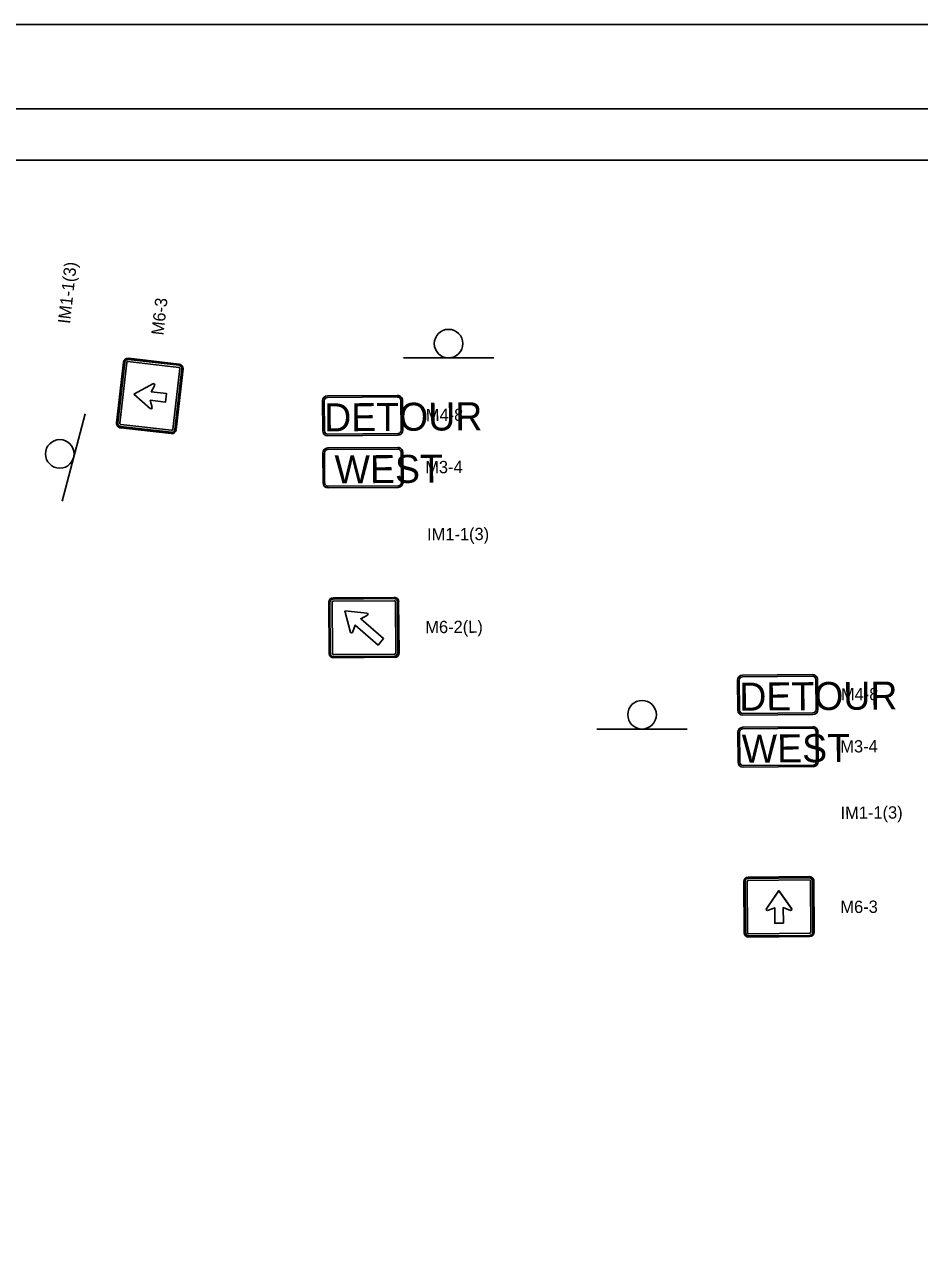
# Model space of a CAD drawing. Extents: x 2162123 to 2216123, y 180770 to 216770.
# Drawn here: x 2190113 to 2203225, y 198770 to 216770 of the extents above; entities that cross this region are included whole.
import ezdxf

# ---------------------------------------------------------------- set-up
doc = ezdxf.new("R2010")
doc.units = 0
for name, color, linetype in [('Default', 7, 'Continuous'), ('PR_Phasing_Detour_1', 7, 'Continuous'), ('SHT_Plot_Shape_Full', 7, 'Continuous'), ('SHT_Plot_Shape_Half', 7, 'Continuous'), ('SHT_Section_Layout_Block', 7, 'Continuous'), ('SHT_Sheet_Border', 7, 'Continuous')]:
    doc.layers.add(name, color=color, linetype=linetype)

# ---------------------------------------------------------------- blocks, each defined once
blk = doc.blocks.new('PRSIGN')
at = {"layer": 'Default'}
blk.add_line((20.04, 6.36), (-20.04, 6.36), dxfattribs=at)
blk.add_circle((0, 0), 6.35, dxfattribs=at)

msp = doc.modelspace()

# ---------------------------------------------------------------- linework, layer by layer
at = {"layer": 'PR_Phasing_Detour_1'}
for p, q in [((2192378, 211793), (2191634, 211877)), ((2191562, 211820), (2191461, 210930)), ((2191580, 211818), (2191479, 210928)), ((2191580, 211818), (2191479, 210928)), ((2191510, 210924), (2191610, 211814)), ((2191510, 210924), (2191610, 211814)), ((2191628, 211828), (2192373, 211744)), ((2191628, 211828), (2192373, 211744)), ((2192376, 211775), (2191632, 211859)), ((2192376, 211775), (2191632, 211859)), ((2192387, 211726), (2192286, 210836)), ((2192387, 211726), (2192286, 210836)), ((2192317, 210833), (2192417, 211723)), ((2192317, 210833), (2192417, 211723)), ((2192335, 210831), (2192435, 211721)), ((2192002, 211508), (2191712, 211352)), ((2191712, 211352), (2191960, 211136)), ((2191967, 211386), (2192020, 211485)), ((2192192, 211361), (2191967, 211386)), ((2192178, 211236), (2192192, 211361)), ((2195577, 211334), (2194551, 211326)), ((2191983, 211154), (2191953, 211262)), ((2191953, 211262), (2192178, 211236)), ((2194478, 211252), (2194482, 210813)), ((2194503, 211253), (2194506, 210813)), ((2195577, 211310), (2194551, 211302)), ((2195630, 210822), (2195626, 211262)), ((2195654, 210822), (2195651, 211262)), ((2191518, 210858), (2192263, 210774)), ((2191521, 210876), (2192265, 210792)), ((2191521, 210876), (2192265, 210792)), ((2192268, 210822), (2191524, 210906)), ((2192268, 210822), (2191524, 210906)), ((2194556, 210765), (2195581, 210773)), ((2194556, 210740), (2195581, 210748)), ((2194482, 210489), (2194486, 210049)), ((2194507, 210489), (2194510, 210049)), ((2195581, 210571), (2194555, 210563)), ((2195581, 210546), (2194555, 210538)), ((2195634, 210058), (2195630, 210498)), ((2195658, 210059), (2195655, 210498)), ((2194560, 210001), (2195585, 210009)), ((2194560, 209976), (2195585, 209985)), ((2194569, 208300), (2194575, 207551)), ((2194587, 208300), (2194593, 207551)), ((2194587, 208300), (2194593, 207551)), ((2194624, 207551), (2194618, 208300)), ((2194624, 207551), (2194618, 208300)), ((2195529, 208373), (2194633, 208365)), ((2195529, 208354), (2194633, 208347)), ((2195529, 208354), (2194633, 208347)), ((2194634, 208317), (2195529, 208324)), ((2194634, 208317), (2195529, 208324)), ((2195546, 208308), (2195552, 207559)), ((2195546, 208308), (2195552, 207559)), ((2195582, 207559), (2195576, 208308)), ((2195582, 207559), (2195576, 208308)), ((2195601, 207559), (2195594, 208308)), ((2195135, 208140), (2194808, 208175)), ((2194808, 208175), (2194890, 207856)), ((2195536, 207542), (2194640, 207535)), ((2195536, 207542), (2194640, 207535)), ((2194640, 207505), (2195536, 207512)), ((2194640, 207505), (2195536, 207512)), ((2194640, 207486), (2195536, 207494)), ((2201659, 207241), (2200633, 207232)), ((2201659, 207216), (2200633, 207208)), ((2200560, 207159), (2200564, 206719)), ((2200585, 207159), (2200588, 206719)), ((2201712, 206728), (2201708, 207168)), ((2201736, 206728), (2201733, 207168)), ((2200638, 206671), (2201663, 206679)), ((2200638, 206646), (2201663, 206655)), ((2201663, 206477), (2200637, 206469)), ((2200564, 206395), (2200568, 205955)), ((2200589, 206395), (2200592, 205955)), ((2201663, 206453), (2200637, 206444)), ((2201716, 205965), (2201712, 206404)), ((2201740, 205965), (2201737, 206404)), ((2200642, 205907), (2201667, 205915)), ((2200642, 205883), (2201667, 205891)), ((2200651, 204206), (2200657, 203457)), ((2200669, 204206), (2200675, 203457)), ((2200669, 204206), (2200675, 203457)), ((2200706, 203457), (2200700, 204207)), ((2200706, 203457), (2200700, 204207)), ((2201611, 204279), (2200715, 204272)), ((2201611, 204260), (2200715, 204253)), ((2201611, 204260), (2200715, 204253)), ((2200716, 204223), (2201611, 204230)), ((2200716, 204223), (2201611, 204230)), ((2201628, 204214), (2201634, 203465)), ((2201628, 204214), (2201634, 203465)), ((2201664, 203465), (2201658, 204214)), ((2201664, 203465), (2201658, 204214)), ((2201683, 203465), (2201676, 204214)), ((2201165, 204074), (2200980, 203802)), ((2201354, 203805), (2201165, 204074)), ((2201001, 203781), (2201104, 203823)), ((2201104, 203823), (2201106, 203597)), ((2201231, 203598), (2201229, 203824)), ((2201229, 203824), (2201334, 203784)), ((2201106, 203597), (2201231, 203598)), ((2201618, 203449), (2200722, 203441)), ((2201618, 203449), (2200722, 203441)), ((2200722, 203411), (2201618, 203418)), ((2200722, 203411), (2201618, 203418)), ((2200722, 203392), (2201618, 203400))]:
    msp.add_line(p, q, dxfattribs=at)
for points in [[(2192003, 211508), (2191713, 211352)], [(2191713, 211352), (2191960, 211135)], [(2191983, 211154), (2191954, 211262), (2192179, 211236), (2192193, 211361), (2191968, 211386), (2192021, 211485)], [(2194808, 208175), (2194890, 207856)], [(2195135, 208140), (2194808, 208175)], [(2194920, 207858), (2194956, 207964), (2195293, 207674), (2195374, 207768), (2195038, 208059), (2195137, 208110)], [(2194920, 207858), (2194956, 207964), (2195293, 207674), (2195374, 207768), (2195038, 208059), (2195137, 208110)], [(2201165, 204073), (2200980, 203801)], [(2201354, 203804), (2201165, 204073)], [(2201001, 203780), (2201104, 203823), (2201106, 203596), (2201231, 203597), (2201229, 203824), (2201334, 203783)]]:
    msp.add_lwpolyline(points, dxfattribs=at)
for centre, radius, start, end in [((2191626, 211812), 64.9, 83.5468, 173.5468), ((2191626, 211812), 46.6, 83.5468, 173.5468), ((2191626, 211812), 46.6, 83.5468, 173.5468), ((2191626, 211812), 16.1, 83.5468, 173.5468), ((2191626, 211812), 16.1, 83.5468, 173.5468), ((2192371, 211728), 16.1, 353.5468, 83.5468), ((2192371, 211728), 16.1, 353.5468, 83.5468), ((2192371, 211728), 46.6, 353.5468, 83.5468), ((2192371, 211728), 46.6, 353.5468, 83.5468), ((2192371, 211728), 64.9, 353.5468, 83.5468), ((2191999, 211487), 20.8, 353.5468, 83.5468), ((2192000, 211487), 20.8, 353.5468, 83.5468), ((2194552, 211253), 73.3, 90.4611, 180.4611), ((2195577, 211261), 73.3, 0.4611, 90.4611), ((2191963, 211156), 20.8, 263.5468, 353.5468), ((2191962, 211156), 20.8, 263.5468, 353.5468), ((2194552, 211253), 48.8, 90.4611, 180.4611), ((2195577, 211261), 48.8, 0.4611, 90.4611), ((2191526, 210922), 64.9, 173.5468, 263.5468), ((2191526, 210922), 46.6, 173.5468, 263.5468), ((2191526, 210922), 46.6, 173.5468, 263.5468), ((2191526, 210922), 16.1, 173.5468, 263.5468), ((2191526, 210922), 16.1, 173.5468, 263.5468), ((2192270, 210838), 64.9, 263.5468, 353.5468), ((2192270, 210838), 46.6, 263.5468, 353.5468), ((2192270, 210838), 46.6, 263.5468, 353.5468), ((2192270, 210838), 16.1, 263.5468, 353.5468), ((2192270, 210838), 16.1, 263.5468, 353.5468), ((2194555, 210813), 73.3, 180.4611, 270.4611), ((2194555, 210813), 48.8, 180.4611, 270.4611), ((2195581, 210822), 73.3, 270.4611, 0.4611), ((2195581, 210822), 48.8, 270.4611, 0.4611), ((2194556, 210489), 73.3, 90.4611, 180.4611), ((2194556, 210489), 48.8, 90.4611, 180.4611), ((2195581, 210498), 73.3, 0.4611, 90.4611), ((2195581, 210498), 48.8, 0.4611, 90.4611), ((2194559, 210050), 73.3, 180.4611, 270.4611), ((2194559, 210050), 48.8, 180.4611, 270.4611), ((2195585, 210058), 73.3, 270.4611, 0.4611), ((2195585, 210058), 48.8, 270.4611, 0.4611), ((2194634, 208301), 64.9, 90.4611, 180.4611), ((2194634, 208301), 46.6, 90.4611, 180.4611), ((2194634, 208301), 46.6, 90.4611, 180.4611), ((2194634, 208301), 16.1, 90.4611, 180.4611), ((2194634, 208301), 16.1, 90.4611, 180.4611), ((2195530, 208308), 64.9, 0.4611, 90.4611), ((2195530, 208308), 46.6, 0.4611, 90.4611), ((2195530, 208308), 46.6, 0.4611, 90.4611), ((2195530, 208308), 16.1, 0.4611, 90.4611), ((2195530, 208308), 16.1, 0.4611, 90.4611), ((2195122, 208124), 20.8, 319.2024, 49.2024), ((2195122, 208124), 20.8, 319.2024, 49.2024), ((2194904, 207872), 20.8, 229.2024, 319.2024), ((2194904, 207872), 20.8, 229.2024, 319.2024), ((2194640, 207551), 64.9, 180.4611, 270.4611), ((2194640, 207551), 46.6, 180.4611, 270.4611), ((2194640, 207551), 46.6, 180.4611, 270.4611), ((2194640, 207551), 16.1, 180.4611, 270.4611), ((2194640, 207551), 16.1, 180.4611, 270.4611), ((2195536, 207558), 64.9, 270.4611, 0.4611), ((2195536, 207558), 46.6, 270.4611, 0.4611), ((2195536, 207558), 16.1, 270.4611, 0.4611), ((2195536, 207558), 46.6, 270.4611, 0.4611), ((2195536, 207558), 16.1, 270.4611, 0.4611), ((2200634, 207159), 73.3, 90.4611, 180.4611), ((2200634, 207159), 48.8, 90.4611, 180.4611), ((2201659, 207167), 73.3, 0.4611, 90.4611), ((2201659, 207167), 48.8, 0.4611, 90.4611), ((2200637, 206720), 73.3, 180.4611, 270.4611), ((2200637, 206720), 48.8, 180.4611, 270.4611), ((2201663, 206728), 73.3, 270.4611, 0.4611), ((2201663, 206728), 48.8, 270.4611, 0.4611), ((2200638, 206395), 73.3, 90.4611, 180.4611), ((2201663, 206404), 73.3, 0.4611, 90.4611), ((2200638, 206395), 48.8, 90.4611, 180.4611), ((2201663, 206404), 48.8, 0.4611, 90.4611), ((2200641, 205956), 73.3, 180.4611, 270.4611), ((2200641, 205956), 48.8, 180.4611, 270.4611), ((2201667, 205964), 48.8, 270.4611, 0.4611), ((2201667, 205964), 73.3, 270.4611, 0.4611), ((2200716, 204207), 64.9, 90.4611, 180.4611), ((2200716, 204207), 46.6, 90.4611, 180.4611), ((2200716, 204207), 46.6, 90.4611, 180.4611), ((2200716, 204207), 16.1, 90.4611, 180.4611), ((2200716, 204207), 16.1, 90.4611, 180.4611), ((2201612, 204214), 64.9, 0.4611, 90.4611), ((2201612, 204214), 46.6, 0.4611, 90.4611), ((2201612, 204214), 46.6, 0.4611, 90.4611), ((2201612, 204214), 16.1, 0.4611, 90.4611), ((2201612, 204214), 16.1, 0.4611, 90.4611), ((2201000, 203802), 20.8, 180.4611, 270.4611), ((2201000, 203801), 20.8, 180.4611, 270.4611), ((2201333, 203804), 20.8, 270.4611, 0.4611), ((2201333, 203804), 20.8, 270.4611, 0.4611), ((2200722, 203457), 64.9, 180.4611, 270.4611), ((2200722, 203457), 46.6, 180.4611, 270.4611), ((2200722, 203457), 46.6, 180.4611, 270.4611), ((2200722, 203457), 16.1, 180.4611, 270.4611), ((2200722, 203457), 16.1, 180.4611, 270.4611), ((2201618, 203465), 64.9, 270.4611, 0.4611), ((2201618, 203465), 46.6, 270.4611, 0.4611), ((2201618, 203465), 16.1, 270.4611, 0.4611), ((2201618, 203465), 46.6, 270.4611, 0.4611), ((2201618, 203465), 16.1, 270.4611, 0.4611)]:
    msp.add_arc(centre, radius, start, end, dxfattribs=at)
at = {"layer": 'SHT_Plot_Shape_Full'}
msp.add_lwpolyline([(2162123, 216770), (2216123, 216770), (2216123, 180770), (2162123, 180770)], close=True, dxfattribs=at)
at = {"layer": 'SHT_Plot_Shape_Half'}
msp.add_lwpolyline([(2164579, 215532), (2215579, 215532), (2215579, 182532), (2164579, 182532)], close=True, dxfattribs=at)
at = {"layer": 'SHT_Section_Layout_Block'}
msp.add_lwpolyline([(2167504, 183282), (2167504, 214782), (2208387, 214782), (2208387, 211973), (2214628, 211973), (2214754, 185757), (2203354, 185757), (2203354, 183282)], close=True, dxfattribs=at)
at = {"layer": 'SHT_Sheet_Border'}
msp.add_lwpolyline([(2214754, 183282), (2167504, 183282), (2167504, 214782), (2214754, 214782)], close=True, dxfattribs=at)

# ---------------------------------------------------------------- block references
at = {"layer": 'PR_Phasing_Detour_1'}
for p, xscale, yscale, rotation in [((2196325, 212092), 33, 33, 180), ((2190629, 210476), 32.99999999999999, 33.00000000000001, -104.78332417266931), ((2199161, 206652), 33, 33, 180)]:
    msp.add_blockref('PRSIGN', p, dxfattribs=dict(at, xscale=xscale, yscale=yscale, rotation=rotation))

# ---------------------------------------------------------------- texts
for s, height, rotation, p in [('IM1-1(3)', 180, 83.5468, (2190778, 212377)), ('M6-3', 180, 83.5468, (2192147, 212208)), ('DETOUR', 410.3, 0.4611, (2194505, 210805)), ('M4-8', 180, 0.4611, (2195993, 210955)), ('WEST', 410.3, 0.4611, (2194658, 210042)), ('M3-4', 180, 0.4611, (2195984, 210191)), ('IM1-1(3)', 180, 0.4611, (2196011, 209206)), ('M6-2(L)', 180, 0.4611, (2195985, 207847)), ('DETOUR', 410.3, 0.4611, (2200587, 206711)), ('M4-8', 180, 0.4611, (2202075, 206861)), ('WEST', 410.3, 0.4611, (2200624, 205948)), ('M3-4', 180, 0.4611, (2202066, 206097)), ('IM1-1(3)', 180, 0.4611, (2202070, 205124)), ('M6-3', 180, 0.4611, (2202067, 203744))]:
    msp.add_text(s, height=height, rotation=rotation, dxfattribs=at).set_placement(p)

doc.saveas('drawing.dxf')
